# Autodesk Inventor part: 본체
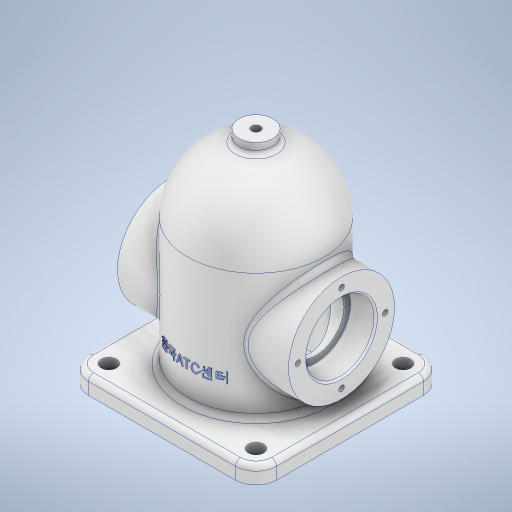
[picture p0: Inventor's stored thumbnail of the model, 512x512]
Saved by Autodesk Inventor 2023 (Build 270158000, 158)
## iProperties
Created: 2025-04
Part Number: 본체
Material: 알루미늄 6061
Document SubType Name: Modeling
Designer: user
Mass: 865.906 g
Surface Area: 800.755 cm^2
Volume: 320.706 cm^3
Density: 2.7 g/cm^3
Appearance: 알루미늄 - 평지
Author: user
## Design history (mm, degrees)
sketch "스케치1"
  geometry: L1 (-57.941, 0)-(9.657, 0) reference; L2 (0, -26.457)-(0, 158.741) reference; L3 (0, 0)-(-40, 0); L4 (-40, 0)-(-40, 84); L5 (-40, 84)-(0, 84); L6 (0, 84)-(0, 0); L7 (0, 124)-(0, 0); A1 r 40 centre (0, 84) between (0, 124) and (-40, 84); 2 further points
  constraints: 10 end point, 3 point on line, 2 parallel, 2 perpendicular, 2 point on circle, 1 centre point, 1 coincident, 1 horizontal, 1 midpoint
  dimensions: "d0" = 84 distance from line of point (-20, 0) L5; "d1" = 40 radius of A1
revolve "회전1" sketch "스케치1" stored, may be unused: angle "d2" = 90 deg
sketch "스케치2"
  geometry: L1 (-24.8, 0)-(148.8, 0) reference; L2 (0, -56)-(0, 56) reference; C1 r 31 at (48, 0); 1 further point
  constraints: 1 centre point, 1 horizontal alignment
  dimensions: "d3" = 62 diameter of C1; "d4" = 48 distance from line of L2 C1.centre
extrude "돌출1" join sketch "스케치2" stored distance "d5" = 100; taper "d6" = 0 deg
sketch "스케치3"
  geometry: L1 (-55, 55)-(55, 55); L2 (55, 55)-(55, -55); L3 (55, -55)-(-55, -55); L4 (-55, -55)-(-55, 55); L5 (-55, 55)-(55, -55); L6 (55, 55)-(-55, -55); 1 further point
  constraints: 12 end point, 2 midpoint, 2 parallel, 1 horizontal, 1 perpendicular
  dimensions: "d7" = 110 distance of L1.end L2.end; "d8" = 110 distance of L2.end L3.end
extrude "돌출2" join sketch "스케치3" distance "d9" = 10; taper "d10" = 0 deg
sketch "스케치5"
  geometry: L1 (40, 84)-(40, 79) reference; L2 (40, 79)-(50, 79) reference; L3 (50, 79)-(50, 17) reference; L4 (50, 17)-(40, 17) reference; L5 (40, 17)-(40, 10) reference; L6 (40, 10)-(55, 10) reference; L7 (55, 10)-(55, 0) reference; L8 (55, 0)-(-55, 0) reference; L9 (-55, 0)-(-55, 10) reference; L10 (-55, 10)-(-40, 10) reference; L11 (-40, 10)-(-40, 17) reference; L12 (-40, 17)-(-50, 17) reference; L13 (-50, 17)-(-50, 79) reference; L14 (-50, 79)-(-40, 79) reference; L15 (-40, 79)-(-40, 84) reference; L16 (32, 84)-(32, 0); L17 (55, 0)-(-55, 0) reference; L18 (0, 116)-(0, 0); L19 (32, 0)-(0, 0); L20 (0, -26.457)-(0, 158.741) reference; A1 r 40 centre (0, 84) between (40, 84) and (0, 124) reference; A2 r 40 centre (0, 84) between (0, 124) and (-40, 84) reference; A3 r 32 centre (0, 84) between (32, 84) and (0, 116); 1 further point
  constraints: 6 end point, 2 point on circle, 1 centre point, 1 collinear, 1 perpendicular, 1 point on line, 1 vertical
  dimensions: "d12" = 32 radius of A3; "d13" = 84 distance of L16.start L16.end
revolve "회전2" sketch "스케치5" stored, may be unused: angle "d14" = 90 deg
sketch "스케치6"
  geometry: C1 r 20 at (0, 0); C2 r 31 at (0, 0) reference; 1 further point
  constraints: 1 centre point, 1 concentric
  dimensions: "d15" = 40 diameter of C1
extrude "돌출3" cut sketch "스케치6" distance "d16" = 15; taper "d17" = 0 deg
sketch "스케치8"
  geometry: C1 r 16.5 at (0, 0); C2 r 20 at (0, 0) reference; 1 further point
  constraints: 1 centre point, 1 concentric
  dimensions: "d18" = 33 diameter of C1
extrude "돌출4" cut sketch "스케치8" extent not by distance; stored distance "d19" = 0; taper "d20" = 0 deg
node "작업 평면1"
sketch "스케치9"
  geometry: C1 r 32 at (55, 55) reference; C2 r 10 at (55, 55); 1 further point
  constraints: 1 centre point, 1 coincident
  dimensions: "d22" = 20 diameter of C2
extrude "돌출5" join sketch "스케치9" stored distance "d23" = 10; taper "d24" = 0 deg
sketch "스케치10" dims "d25" = 51
  geometry: L1 (0, -72.8)-(0, 100.8) reference; C1 r 20 at (0, 0) reference; 3 further points
  constraints: 2 vertical alignment, 3 other
hole "구멍1" sketch "스케치10" at (0, 25.5) diameter "d26" = 3.242; stored, may be unused: countersink angle "d30" = 90 deg, drill point angle "d32" = 118 deg; dims "d27" = 8, "d28" = 4, "d29" = 2, "d31" = 10
sketch "스케치11"
  geometry: 2 further points
  constraints: 1 coincident
hole "구멍2" sketch "스케치11" at (0, 0) diameter "d36" = 5.1881; stored, may be unused: countersink angle "d40" = 90 deg, drill point angle "d42" = 0 deg; dims "d37" = 12, "d38" = 4, "d39" = 2, "d41" = 16
fillet "모깎기1" dims "d43" = 0.3
fillet "모깎기2" dims "d44" = 12
sketch "스케치12"
  geometry: L1 (0, 77.497)-(0, -79.982) reference; L2 (-79.982, 0)-(77.497, 0) reference; C1 r 4.5 at (-43, -43); C2 r 4.5 at (-43, 43); C3 r 4.5 at (43, 43); C4 r 4.5 at (43, -43); A1 r 12 centre (-43, -43) between (-55, -43) and (-43, -55) reference; 1 further point
  constraints: 4 centre point, 3 symmetric about line, 1 coincident, 3 other
  dimensions: "d45" = 9 diameter of C1
extrude "돌출6" cut sketch "스케치12" extent not by distance; stored distance "d46" = 0; taper "d47" = 0 deg
fillet "모깎기3" dims "d48" = 3
fillet "모깎기4" dims "d49" = 3
fillet "모깎기5" dims "d50" = 3
chamfer "모따기1" distance "d51" = 1; stored, may be unused: second distance "d52" = 2, angle "d53" = 45 deg
node "작업 평면2"
sketch "스케치13"
  geometry: L1 (0, -24.8)-(0, 148.8) reference; L2 (-77, 0)-(77, 0) reference; 2 further points
  constraints: 1 vertical alignment, 1 other
  dimensions: "d55" = 30 distance from line of L2 point (0, 30)
feature "엠보싱1" sketch "스케치13" dims "d7" = 110, "d8" = 110, "d56" = 0.5, "d57" = 0
node "솔리드1"
mirror "미러1"
pattern_circular "원형 패턴1" dims angle "d34" = 360 deg
mirror "미러2"
node "절단 모서리 투영1"
feature "A9D066F2-1C7D-4E18-AEED-F7BC21143FA4" dims "d26" = 3.242, "d27" = 8, "d28" = 4, "d29" = 2, "d30" = 90 deg, "d31" = 10, "d32" = 118 deg
other parameters: "d21" = -129, "d54" = 99.75
